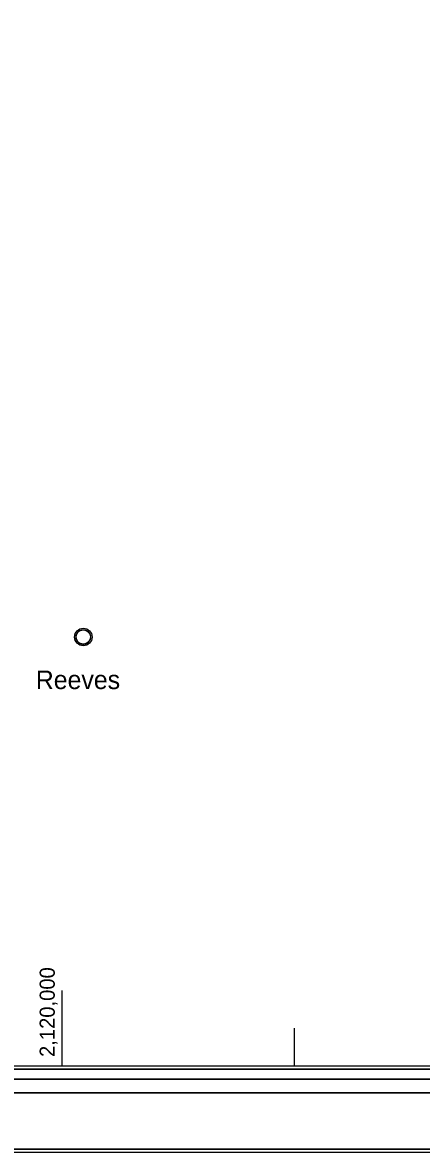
# Model space of a CAD drawing. Extents: x 5197761 to 5514561, y 1890130 to 2080942.
# Drawn here: x 5349083 to 5366240, y 1890130 to 1938803 of the extents above; entities that cross this region are included whole.
import ezdxf

# ---------------------------------------------------------------- set-up
doc = ezdxf.new("R2010")
doc.units = 0
for name, color, linetype in [('Exist Civil Demographics Community CELL', 7, 'Continuous'), ('Exist Civil Demographics Community Label', 7, 'Continuous'), ('Map Preparation Base StatePlane Tick Label', 7, 'Continuous'), ('Map Preparation Base StatePlane Tick Mark', 7, 'Continuous'), ('Map Preparation Border Antique Large Shape', 7, 'Continuous'), ('Map Preparation Border Antique Small Shape', 7, 'Continuous'), ('Map Preparation Border Black Inside Shape', 7, 'Continuous'), ('Map Preparation Border Black Middle Shape', 7, 'Continuous'), ('Map Preparation Border Black Outside Shape', 7, 'Continuous')]:
    doc.layers.add(name, color=color, linetype=linetype)

msp = doc.modelspace()

# ---------------------------------------------------------------- linework, layer by layer
at = {"layer": 'Exist Civil Demographics Community CELL'}
msp.add_lwpolyline([(5351382, 1912383), (5351386, 1912405), (5351393, 1912431), (5351405, 1912460), (5351417, 1912483), (5351430, 1912506), (5351445, 1912526), (5351461, 1912544), (5351479, 1912562), (5351502, 1912581), (5351523, 1912595), (5351543, 1912607), (5351563, 1912616), (5351585, 1912626), (5351607, 1912633), (5351625, 1912638), (5351644, 1912640), (5351661, 1912643), (5351686, 1912644), (5351704, 1912644), (5351726, 1912643), (5351746, 1912640), (5351766, 1912636), (5351786, 1912630), (5351806, 1912623), (5351833, 1912611), (5351858, 1912597), (5351878, 1912583), (5351899, 1912567), (5351912, 1912554), (5351929, 1912537), (5351944, 1912518), (5351956, 1912500), (5351969, 1912480), (5351979, 1912459), (5351987, 1912439), (5351993, 1912419), (5351998, 1912400), (5352003, 1912376), (5352005, 1912357), (5352006, 1912333), (5352005, 1912310), (5352003, 1912288), (5351999, 1912266), (5351993, 1912241), (5351985, 1912218), (5351976, 1912197), (5351964, 1912173), (5351950, 1912152), (5351937, 1912133), (5351920, 1912114), (5351898, 1912094), (5351878, 1912078), (5351858, 1912064), (5351841, 1912054), (5351814, 1912041), (5351785, 1912030), (5351761, 1912025), (5351735, 1912019), (5351717, 1912017), (5351699, 1912016), (5351677, 1912016), (5351660, 1912018), (5351637, 1912021), (5351614, 1912026), (5351595, 1912031), (5351575, 1912039), (5351556, 1912047), (5351541, 1912056), (5351513, 1912072), (5351491, 1912089), (5351471, 1912107), (5351454, 1912127), (5351441, 1912142), (5351429, 1912159), (5351413, 1912188), (5351406, 1912202), (5351399, 1912218), (5351388, 1912251), (5351382, 1912279), (5351380, 1912299), (5351378, 1912325), (5351378, 1912343), (5351380, 1912369)], close=True, dxfattribs=at)
for centre, radius in [((5351693, 1912333), 377), ((5351692, 1912334), 307)]:
    msp.add_circle(centre, radius, dxfattribs=at)
at = {"layer": 'Map Preparation Base StatePlane Tick Mark'}
for p, q in [((5350787, 1893858), (5350787, 1897109)), ((5360787, 1893858), (5360787, 1895484))]:
    msp.add_line(p, q, dxfattribs=at)
at = {"layer": 'Map Preparation Border Antique Large Shape'}
msp.add_lwpolyline([(5197907, 2074783), (5207205, 2074783), (5207205, 1892697), (5512539, 1892697), (5512539, 2072359), (5207205, 2072359), (5207205, 2074783), (5514414, 2074783), (5514414, 1890276), (5197907, 1890276)], close=True, dxfattribs=at)
at = {"layer": 'Map Preparation Border Antique Small Shape'}
msp.add_lwpolyline([(5207791, 2071720), (5208220, 2071720), (5208220, 1893712), (5511524, 1893712), (5511524, 2071291), (5208220, 2071291), (5208220, 2071720), (5207791, 2071720), (5511953, 2071720), (5511953, 1893283), (5208220, 1893283), (5207791, 1893283)], close=True, dxfattribs=at)
at = {"layer": 'Map Preparation Border Black Inside Shape'}
msp.add_lwpolyline([(5208220, 2071291), (5511524, 2071291), (5511524, 1893712), (5208366, 1893712), (5208366, 1893858), (5511378, 1893858), (5511378, 2071145), (5208366, 2071145), (5208366, 1893858), (5208366, 1893712), (5208220, 1893712), (5208220, 1893858)], close=True, dxfattribs=at)
at = {"layer": 'Map Preparation Border Black Middle Shape'}
msp.add_lwpolyline([(5207205, 2072359), (5512539, 2072359), (5512539, 1892697), (5511953, 1892697), (5207791, 1892697), (5207791, 1893283), (5511953, 1893283), (5511953, 2071720), (5207791, 2071720), (5207791, 1892697), (5207205, 1892697)], close=True, dxfattribs=at)
at = {"layer": 'Map Preparation Border Black Outside Shape'}
msp.add_lwpolyline([(5197761, 2074930), (5514561, 2074930), (5514561, 1890130), (5197907, 1890130), (5197907, 1890276), (5514414, 1890276), (5514414, 2074783), (5197907, 2074783), (5197907, 1890130), (5197761, 1890130)], close=True, dxfattribs=at)

# ---------------------------------------------------------------- texts
at = {"layer": 'Exist Civil Demographics Community Label'}
msp.add_text('Reeves', height=800, dxfattribs=at).set_placement((5349650, 1910090))
at = {"layer": 'Map Preparation Base StatePlane Tick Label'}
msp.add_text('2,120,000', height=650, rotation=90, dxfattribs=at).set_placement((5350466, 1894241))

doc.saveas('drawing.dxf')
